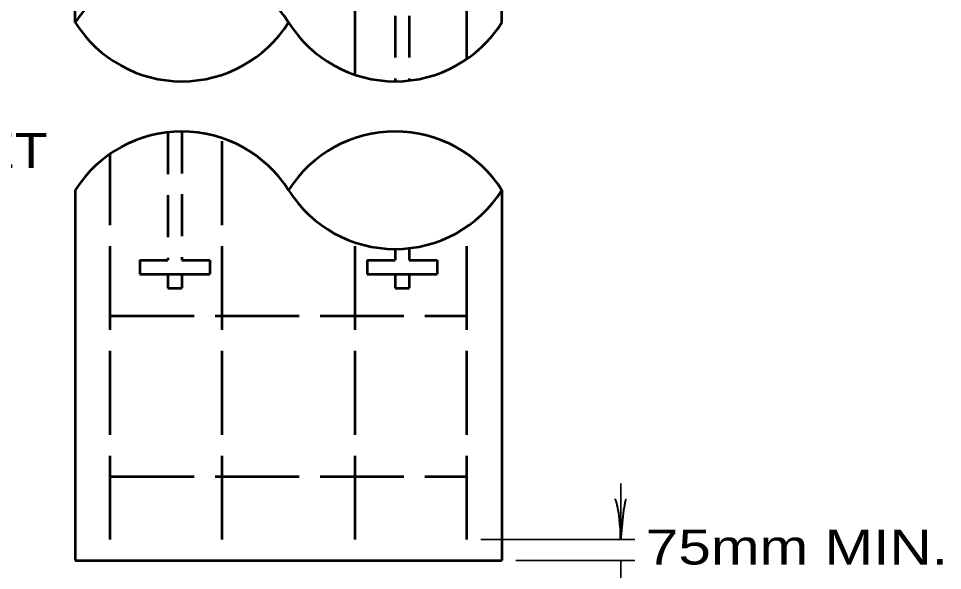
# Model space of a CAD drawing. Extents: x -111 to 744, y -77 to 467.
# Drawn here: x 209.8 to 289, y 115 to 162.4 of the extents above; entities that cross this region are included whole.
import ezdxf

# ---------------------------------------------------------------- set-up
doc = ezdxf.new("R2010")
doc.units = 0
doc.header["$LTSCALE"] = 1.2
doc.linetypes.add('LONG_DASHED', pattern=[7.5, 6, -1.5])
doc.linetypes.add('MEDIUM_DASHED', pattern=[4.5, 3, -1.5])
doc.layers.add('1', color=7, linetype='Continuous', lineweight=53)

msp = doc.modelspace()

# ---------------------------------------------------------------- linework, layer by layer
at = {"layer": '1', "linetype": 'MEDIUM_DASHED'}
for p, q in [((242.089, 216.618), (242.089, 156.981)), ((243.289, 216.618), (243.289, 157.048)), ((222.589, 152.613), (222.589, 141.631)), ((223.789, 152.68), (223.789, 141.631)), ((242.089, 142.581), (242.089, 141.631)), ((243.289, 142.648), (243.289, 141.631)), ((222.589, 140.43), (222.589, 139.231)), ((223.789, 140.43), (223.789, 139.231)), ((242.089, 140.43), (242.089, 139.231)), ((243.289, 140.43), (243.289, 139.231))]:
    msp.add_line(p, q, dxfattribs=at)
at = {"layer": '1', "linetype": 'LONG_DASHED'}
for p, q in [((238.639, 157.546), (238.639, 213.618)), ((248.239, 158.9), (248.239, 213.618)), ((227.239, 117.631), (227.239, 152.115)), ((217.639, 117.631), (217.639, 150.761)), ((248.239, 117.631), (248.239, 144.5)), ((238.639, 117.631), (238.639, 143.146)), ((220.189, 141.631), (220.189, 140.43)), ((220.189, 141.631), (222.589, 141.631)), ((223.789, 141.631), (226.189, 141.631)), ((226.189, 141.631), (226.189, 140.43)), ((239.689, 141.631), (239.689, 140.43)), ((239.689, 141.631), (242.089, 141.631)), ((243.289, 141.631), (245.689, 141.631)), ((245.689, 141.631), (245.689, 140.43)), ((220.189, 140.43), (226.189, 140.43)), ((239.689, 140.43), (245.689, 140.43)), ((222.589, 139.231), (223.789, 139.231)), ((242.089, 139.231), (243.289, 139.231)), ((217.639, 136.831), (248.239, 136.831)), ((217.639, 123.031), (248.239, 123.031))]:
    msp.add_line(p, q, dxfattribs=at)
at = {"layer": '1'}
for p, q in [((251.239, 162.031), (251.239, 213.618)), ((214.639, 147.631), (214.639, 115.831)), ((251.239, 147.631), (251.239, 115.831)), ((214.639, 115.831), (251.239, 115.831))]:
    msp.add_line(p, q, dxfattribs=at)
at = {"layer": '1', "lineweight": 35}
for p, q in [((261.439, 117.631), (261.439, 122.431)), ((249.439, 117.631), (262.639, 117.631)), ((252.439, 115.831), (262.639, 115.831)), ((261.439, 115.831), (261.439, 111.031))]:
    msp.add_line(p, q, dxfattribs=at)
at = {"layer": '1'}
msp.add_lwpolyline([(214.639, 162.031), (214.639, 213.618), (251.239, 213.618)], dxfattribs=at)
for centre, start, end in [((223.789, 156.264), 32.21778, 147.78221), ((223.789, 167.797), 212.21779, 327.78222), ((242.089, 167.797), 212.21779, 327.78222), ((223.789, 141.864), 32.21779, 147.78222), ((242.089, 141.864), 32.21779, 147.78222), ((242.089, 153.397), 212.21778, 327.78221)]:
    msp.add_arc(centre, 10.815, start, end, dxfattribs=at)
at = {"layer": '1', "lineweight": 40}
for centre, major_axis, ratio, start_param, end_param in [((261.108, 118.94), (0.187, -2.143), 0.122415, 0.896353, 3.141593), ((261.693, 118.975), (-0.211, -2.108), 0.07063, 3.140715, 5.41811)]:
    msp.add_ellipse(centre, major_axis=major_axis, ratio=ratio, start_param=start_param, end_param=end_param, dxfattribs=at)

# ---------------------------------------------------------------- texts
at = {"layer": '1'}
for s, width, p in [('THIS SHEET', 1.15, (185.099, 149.534)), ('75mm MIN.', 1.25, (263.589, 115.486))]:
    msp.add_text(s, height=3, dxfattribs=dict(at, width=width)).set_placement(p)

doc.saveas('drawing.dxf')
